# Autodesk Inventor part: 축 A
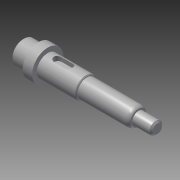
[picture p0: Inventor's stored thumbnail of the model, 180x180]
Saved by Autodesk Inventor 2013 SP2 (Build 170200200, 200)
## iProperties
Created: 2020-04
Part Number: 축 A
Material: 강철, 연강
Document SubType Name: Modeling
Designer: mduedu
Density: 7.86 g/cm^3
Mass: 91.1355 g
Surface Area: 41.2026 cm^2
Volume: 11.5948 cm^3
Author: mduedu
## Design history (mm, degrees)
sketch "스케치1"
  geometry: L1 (0, 0)-(10, 0); L2 (10, 0)-(10, 7.5); L3 (10, 7.5)-(0, 7.5); L4 (0, 7.5)-(0, 0); L5 (10, 0)-(16, 0); L6 (16, 0)-(16, 10); L7 (16, 10)-(10, 10); L8 (10, 10)-(10, 0); L9 (16, 0)-(41, 0); L10 (41, 0)-(41, 7); L11 (41, 7)-(16, 7); L12 (16, 7)-(16, 0); L13 (41, 0)-(74, 0); L14 (74, 0)-(74, 6); L15 (74, 6)-(41, 6); L16 (41, 6)-(41, 0); L17 (74, 0)-(86, 0); L18 (86, 0)-(86, 4); L19 (86, 4)-(74, 4); L20 (74, 4)-(74, 0)
  constraints: 40 end point, 10 parallel, 5 horizontal, 5 perpendicular
  dimensions: "d0" = 86 distance between parallel lines of L18 L4; "d2" = 10 distance of L2.end L3.end; "d3" = 6 distance of L6.end L7.end; "d4" = 12 distance of L18.end L19.end; "d5" = 8 diameter of L19 L17; "d6" = 12 diameter of L15 L13; "d7" = 14 diameter of L11 L9; "d8" = 15 diameter of L3 L1; "d9" = 20 diameter of L7 L5; "d10" = 45 distance between parallel lines of L10 L18
revolve "회전1" sketch "스케치1" stored, may be unused: angle "d11" = 90 deg
sketch "스케치2"
  geometry: L1 (0, -7.5)-(0, 7.5) reference; L2 (0, 7.5)-(10, 7.5) reference; L3 (10, 7.5)-(10, 10) reference; L4 (10, 10)-(16, 10) reference; L5 (16, 10)-(16, 7) reference; L6 (16, 7)-(41, 7) reference; L7 (41, 7)-(41, 6) reference; L8 (41, 6)-(74, 6) reference; L9 (74, 6)-(74, 4) reference; L10 (74, 4)-(86, 4) reference; L11 (86, 4)-(86, -4) reference; L12 (86, -4)-(74, -4) reference; L13 (74, -4)-(74, -6) reference; L14 (74, -6)-(41, -6) reference; L15 (41, -6)-(41, -7) reference; L16 (41, -7)-(16, -7) reference; L17 (16, -7)-(16, -10) reference; L18 (16, -10)-(10, -10) reference; L19 (10, -10)-(10, -7.5) reference; L20 (10, -7.5)-(0, -7.5) reference; L21 (86, -4)-(78, -4); L22 (78, -4)-(78, -2.8); L23 (78, -2.8)-(86, -2.8); L24 (86, -2.8)-(86, -4); 1 further point
  constraints: 8 end point, 2 parallel, 1 horizontal, 1 perpendicular
  dimensions: "d12" = 8 distance of L22.end L23.end; "d13" = 1.2 distance of L21.end L22.end
extrude "돌출1" cut sketch "스케치2" stored distance "d14" = 2; taper "d15" = 0 deg
fillet "모깎기1" dims "d16" = 1
sketch "스케치3"
  geometry: L1 (0, -7.5)-(0, 7.5) reference; L2 (0, 7.5)-(10, 7.5) reference; L3 (10, 7.5)-(10, 10) reference; L4 (10, 10)-(16, 10) reference; L5 (16, 10)-(16, 7) reference; L6 (16, 7)-(41, 7) reference; L7 (41, 7)-(41, 6) reference; L8 (41, 6)-(74, 6) reference; L9 (74, 6)-(74, 4) reference; L10 (74, 4)-(86, 4) reference; L11 (86, 4)-(86, -2.8) reference; L12 (86, -2.8)-(78, -2.8) reference; L13 (78, -2.8)-(78, -4) reference; L14 (78, -4)-(74, -4) reference; L15 (74, -4)-(74, -6) reference; L16 (74, -6)-(41, -6) reference; L17 (41, -6)-(41, -7) reference; L18 (41, -7)-(16, -7) reference; L19 (16, -7)-(16, -10) reference; L20 (16, -10)-(10, -10) reference; L21 (10, -10)-(10, -7.5) reference; L22 (10, -7.5)-(0, -7.5) reference; L23 (20, 7)-(32, 7); L24 (32, 7)-(32, 4); L25 (32, 4)-(20, 4); L26 (20, 4)-(20, 7); 1 further point
  constraints: 8 end point, 2 parallel, 1 horizontal, 1 perpendicular, 1 point on line
  dimensions: "d17" = 12 distance of L24.end L25.end; "d18" = 3 distance of L23.end L24.end; "d19" = 4 distance from line of L26 L4.end
extrude "돌출2" cut sketch "스케치3" stored distance "d20" = 5; taper "d21" = 0 deg
fillet "모깎기2" dims "d22" = 2.5
chamfer "모따기1" distance "d23" = 1; stored, may be unused: second distance "d24" = 2, angle "d25" = 45 deg
chamfer "모따기2" distance "d26" = 0.5; stored, may be unused: second distance "d27" = 2, angle "d28" = 45 deg
fillet "모깎기3" dims "d29" = 0.3
chamfer "모따기3" distance "d30" = 1.56; stored, may be unused: second distance "d31" = 2, angle "d32" = 30 deg
fillet "모깎기4" dims "d33" = 4, "d34" = 0.5
node "솔리드1"
node "절단 모서리 투영1"
node "절단 모서리 투영2"
